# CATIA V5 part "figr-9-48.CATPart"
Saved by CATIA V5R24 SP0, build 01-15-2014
Part number: Part1
Bounding box of the stored display mesh (mm): x -53.419 to 50, y -50 to 50, z -57.709 to 133.109
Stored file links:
  D:\KAVITA\CATIA V5-6R2014 Project_ Kavita\CATIA V5-6R2014_partfiles\Partfiles\c09_catia_v5-6r2014_prt\figr-9-48.CATPart
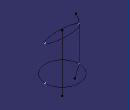
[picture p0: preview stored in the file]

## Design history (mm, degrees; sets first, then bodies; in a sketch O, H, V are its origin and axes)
Body1 (main body)
  Plane1: type Offset, RefPlane xy-plane, Offset 103
  Sketch1 on Plane1, origin (0, 0, 103), H (1, 0, 0), V (0, 1, 0)
    ellipse A1 centre (0, 0) semi-axes 50, 13.2069 rotation 0
    point P1 (50, 0)
    "Radius" A1 = 50
    coincidence: P1 H, A1 P1
  Extremum1: Reference Sketch1, Direction (1, 2, 3)
  Sketch2 on xy-plane, origin (0, 0, 0), H (1, 0, 0), V (0, 1, 0)
    circle A1 centre (0, 0) radius 50
    radius A1 = 50
  Extremum2: Reference Sketch2, Direction (1, 2, 3)
  Sketch3 on zx-plane, origin (0, 0, 0), H (-1, 0, 0), V (0, 0, 1)
    spline S1 through (37.7591, -31.0289) (41.8235, -21.251) (50, 0) (49.8084, 85.7657) (50, 103) (41.6255, 133.1089)
    reference projected line E1 (-50, 103) -> (50, 103) from Sketch1.A1
    point P1 (50, 0)
    point P2 (50, 103)
    distance V P1 = 50
    distance P2 V = 50
    coincidence: P1 H, P2 E1
  Sketch4 on zx-plane, origin (0, 0, 0), H (-1, 0, 0), V (0, 0, 1)
    line L1 (0, 111.062) -> (0, -57.7094)
    point P1 (0, 111.062)
    coincidence: P1 V
    vertical: L1 V
  Loft1: solid, Sections (Sketch1; Sketch2), Spine Sketch4, Guides Sketch3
